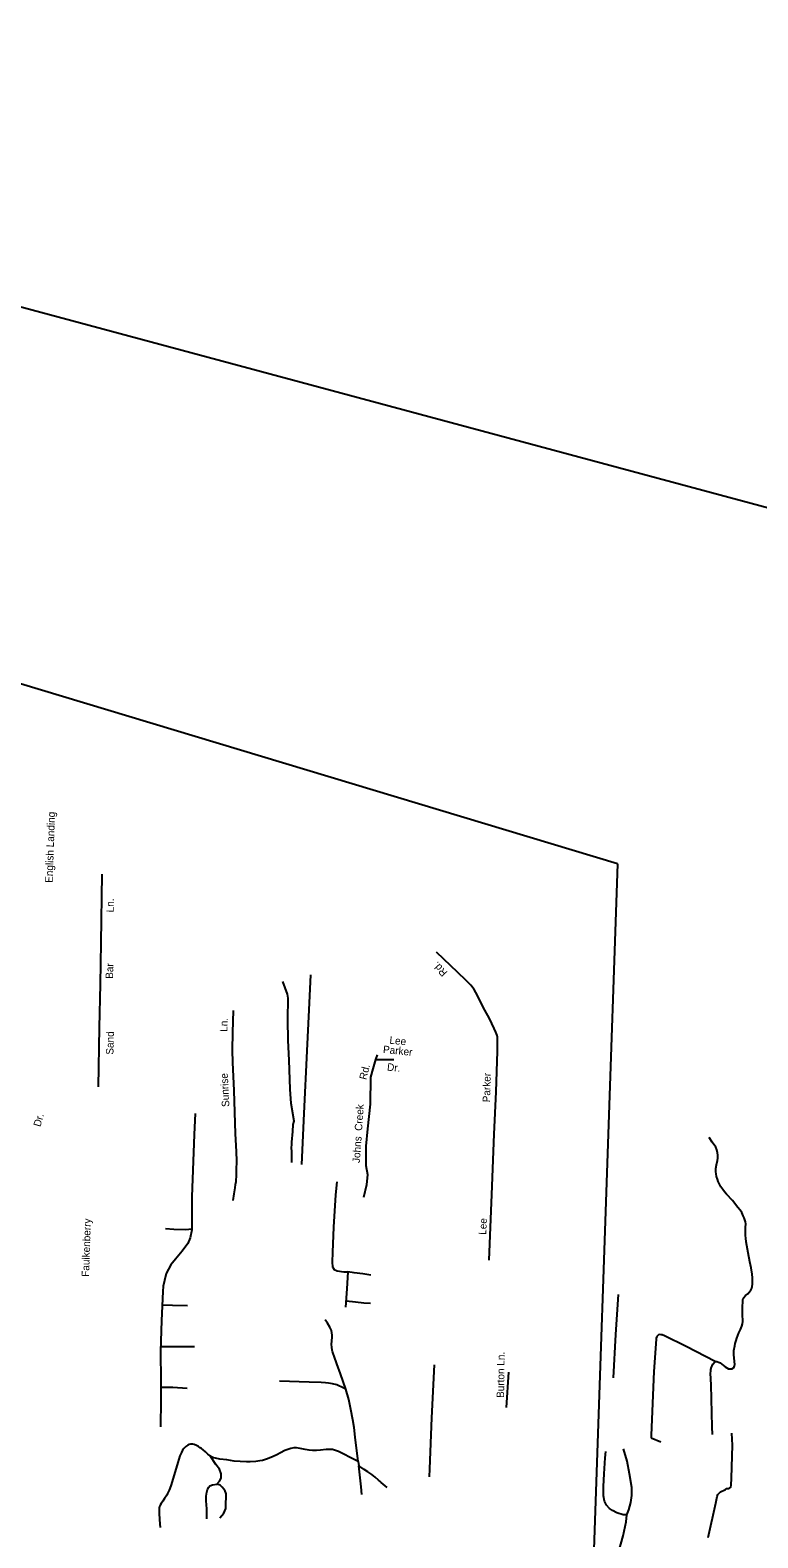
# Model space of a CAD drawing. Extents: x 2308163 to 2335412, y -96774 to 127732.
# Drawn here: x 2321093 to 2321492, y 33932 to 34759 of the extents above; entities that cross this region are included whole.
import ezdxf

# ---------------------------------------------------------------- set-up
doc = ezdxf.new("R2010")
doc.units = 0
for name, color, linetype in [('Old_Level_10', 7, 'Continuous'), ('Old_Level_35', 7, 'Continuous'), ('Old_Level_63', 7, 'Continuous')]:
    doc.layers.add(name, color=color, linetype=linetype)

msp = doc.modelspace()

# ---------------------------------------------------------------- linework, layer by layer
at = {"layer": 'Old_Level_35'}
for p, q in [((2321466.96, 33988.55), (2321466.84, 33992.81)), ((2321433.44, 33988.19), (2321433.38, 33986.76)), ((2321433.38, 33986.76), (2321438.59, 33984.65)), ((2321272.6, 33973.76), (2321272.92, 33971.39)), ((2321274.22, 33959.93), (2321272.92, 33971.39)), ((2321311.78, 33965.37), (2321311.95, 33969.72)), ((2321274.7, 33955.69), (2321274.22, 33959.93)), ((2321163.71, 33941.82), (2321163.94, 33937.59))]:
    msp.add_line(p, q, dxfattribs=at)
for points in [[(2321130.26, 34179.54), (2321130.8, 34212.04), (2321131.25, 34235.79), (2321131.67, 34258.53), (2321132.2, 34296.16)], [(2321344.45, 34084.22), (2321345.93, 34120.3), (2321347.24, 34153.41), (2321348.31, 34176.76), (2321349.1, 34199.01), (2321349.09, 34200.83), (2321349.1, 34203.06), (2321349.11, 34205.26), (2321349.04, 34206.75), (2321348.81, 34207.65), (2321348.23, 34209.41), (2321347.28, 34211.56), (2321344.65, 34216.88), (2321342.14, 34221.56), (2321337.24, 34231.31), (2321336.35, 34232.97), (2321334.47, 34235.25), (2321331.79, 34238.07), (2321327.38, 34242.19), (2321315.52, 34253.34)], [(2321241.64, 34136.86), (2321242.99, 34164.76), (2321244.71, 34199.23), (2321245.74, 34221.72), (2321246.59, 34240.95)], [(2321236.18, 34137.95), (2321236.19, 34143.86), (2321236.14, 34146.21), (2321236.29, 34147.71), (2321236.33, 34149.1), (2321236.83, 34154.95), (2321237.06, 34158.7), (2321237.48, 34160.69), (2321235.95, 34170.36), (2321235.4, 34178.25), (2321234.79, 34194.15), (2321234.18, 34204.91), (2321233.96, 34216.43), (2321234.23, 34228.17), (2321233.79, 34230.32), (2321231.34, 34237.24)], [(2321205.42, 34153.58), (2321204.62, 34177.48), (2321203.87, 34192.76), (2321203.65, 34199.53), (2321203.89, 34209.27), (2321204.3, 34221.4)], [(2321283.04, 34197.1), (2321282.16, 34194.43), (2321280.72, 34189.41), (2321279.44, 34184.7), (2321279.25, 34169.96), (2321277.83, 34156.38), (2321276.87, 34146.9), (2321276.82, 34136.28), (2321277.76, 34131.33), (2321277.25, 34125.64), (2321275.48, 34118.63)], [(2321282.16, 34194.43), (2321292.18, 34194.4)], [(2321183.19, 34164.83), (2321182.6, 34153.21), (2321181.43, 34119.04), (2321181.32, 34105.51), (2321181.31, 34101.05), (2321180.5, 34096.49), (2321179.12, 34093.47), (2321176.12, 34089.29), (2321172.4, 34084.79), (2321169.8, 34081.67), (2321167.35, 34077.05), (2321166.3, 34073.24), (2321165.58, 34070.11), (2321165.48, 34067.05), (2321164.71, 34051.12), (2321164.23, 34034.11), (2321164.39, 34018.07), (2321164.38, 34007.38), (2321164.24, 33992.78)], [(2321204.04, 34117.11), (2321204.62, 34120.72), (2321205.22, 34123.96), (2321205.37, 34125.83), (2321205.67, 34127.45), (2321205.88, 34131.2), (2321205.94, 34133.82), (2321206.08, 34138.66), (2321205.94, 34143.95), (2321205.42, 34153.58)], [(2321468.51, 34028.67), (2321468.9, 34028.68), (2321469.41, 34028.68), (2321470.27, 34028.39), (2321471.38, 34027.87), (2321472.13, 34027.22), (2321473.98, 34025.81), (2321474.94, 34025.14), (2321475.77, 34024.73), (2321476.77, 34024.61), (2321477.69, 34024.7), (2321478.47, 34025.2), (2321478.84, 34025.67), (2321479.1, 34026.33), (2321479.26, 34027.05), (2321478.74, 34032.31), (2321478.78, 34033.68), (2321478.81, 34034.69), (2321479.25, 34037.29), (2321479.53, 34038.55), (2321479.95, 34040.29), (2321480.36, 34041.52), (2321480.88, 34042.9), (2321481.55, 34044.5), (2321482.3, 34046.21), (2321483.13, 34048.1), (2321483.55, 34049.45), (2321483.69, 34050.58), (2321483.61, 34051.58), (2321483.53, 34053.71), (2321483.46, 34055.97), (2321483.53, 34058.96), (2321483.6, 34061.46), (2321483.74, 34062.45), (2321483.83, 34063.25), (2321484.18, 34063.88), (2321485.18, 34064.91), (2321486.32, 34065.88), (2321487.22, 34066.75), (2321487.99, 34067.86), (2321488.54, 34068.89), (2321488.86, 34069.89), (2321488.96, 34071.21), (2321488.97, 34072.58), (2321488.9, 34074.59), (2321488.71, 34076.59), (2321488.18, 34080.1), (2321487.48, 34083.37), (2321486.62, 34088.39), (2321485.5, 34094.43), (2321485.25, 34096.34), (2321485.1, 34097.81), (2321485.05, 34099.7), (2321485.2, 34102.3), (2321485.25, 34104.19), (2321485.14, 34105.31), (2321484.81, 34106.44), (2321484.39, 34107.48), (2321483.85, 34108.73), (2321483.05, 34110.39), (2321482.18, 34111.76), (2321480.96, 34113.29), (2321478.05, 34116.98), (2321474.75, 34120.57), (2321473.66, 34121.84), (2321472.69, 34123.13), (2321471.62, 34124.64), (2321470.85, 34125.99), (2321470.15, 34127.5), (2321469.71, 34128.69), (2321469.25, 34130.32), (2321469.02, 34131.72), (2321468.93, 34132.72), (2321468.92, 34134.61), (2321469.14, 34136.6), (2321469.7, 34139.08), (2321469.94, 34140.31), (2321469.99, 34141.99), (2321469.8, 34143.2), (2321469.34, 34144.96), (2321468.89, 34146.35), (2321466.82, 34149.15), (2321465.13, 34151.56)], [(2321261.01, 34127.38), (2321260.24, 34120.24), (2321259.14, 34102.39), (2321258.51, 34088.76), (2321258.32, 34083.24), (2321258.55, 34080.63), (2321259.48, 34079.13), (2321261.08, 34078.43), (2321264.8, 34077.97), (2321266.92, 34077.9)], [(2321181.31, 34101.38), (2321178.02, 34100.95), (2321171.47, 34101.18), (2321166.89, 34101.55)], [(2321266.92, 34077.9), (2321266.43, 34068.65), (2321265.76, 34058.6)], [(2321279.54, 34076.16), (2321275.17, 34076.8), (2321270.47, 34077.29), (2321266.92, 34077.9)], [(2321412.79, 34019.77), (2321414, 34043.51), (2321415.4, 34065.49)], [(2321165.12, 34059.73), (2321170.69, 34059.66), (2321179, 34059.37)], [(2321265.98, 34061.92), (2321271.23, 34061.5), (2321275.76, 34060.85), (2321279.34, 34060.73)], [(2321265.93, 34013.43), (2321263.02, 34021.91), (2321260.9, 34027.33), (2321259.4, 34031.56), (2321258.84, 34033.16), (2321258.57, 34034.26), (2321258.36, 34034.88), (2321258.11, 34036.52), (2321258.04, 34038.03), (2321258.19, 34040.02), (2321258.37, 34042.01), (2321258.4, 34043.14), (2321258.27, 34044.35), (2321257.96, 34045.66), (2321257.13, 34047.54), (2321255.81, 34049.71), (2321254.61, 34051.48)], [(2321468.51, 34028.67), (2321452.6, 34036.94), (2321440.73, 34042.74), (2321439.5, 34043.27), (2321438.88, 34043.41), (2321438.16, 34043.46), (2321437.4, 34043.26), (2321436.85, 34042.82), (2321436.49, 34042.33), (2321436.18, 34041.51), (2321436.19, 34040.97), (2321434.88, 34023.24), (2321433.44, 33988.19)], [(2321164.31, 34036.86), (2321169.91, 34036.94), (2321182.82, 34036.94)], [(2321311.95, 33969.72), (2321313.07, 33997.68), (2321314.42, 34026.9)], [(2321354.01, 34003.38), (2321355.27, 34022.76)], [(2321466.84, 33992.81), (2321466.22, 34015.85), (2321466, 34022.24), (2321466.02, 34023.37), (2321466.09, 34024.29), (2321466.46, 34025.49), (2321466.82, 34026.35), (2321467.25, 34027.21), (2321468.51, 34028.67)], [(2321178.74, 34013.9), (2321170.88, 34014.39), (2321164.39, 34014.47)], [(2321265.93, 34013.43), (2321263.71, 34014.51), (2321262.11, 34015.28), (2321260.85, 34015.81), (2321258.49, 34016.51), (2321256.38, 34016.81), (2321254.64, 34016.97), (2321252.26, 34017.16), (2321245.76, 34017.31), (2321229.52, 34017.84)], [(2321272.6, 33973.76), (2321270.92, 33987.06), (2321270.42, 33992.47), (2321269.78, 33996.58), (2321268.67, 34002.38), (2321267.43, 34007.91), (2321265.93, 34013.43)], [(2321188.93, 33979.04), (2321187.59, 33980.12), (2321186.6, 33980.84), (2321185.98, 33981.37), (2321185.12, 33982.02), (2321183.99, 33982.59), (2321182.66, 33983.07), (2321181.88, 33983.29), (2321180.67, 33983.37), (2321179.91, 33983.14), (2321179.15, 33982.79), (2321178.13, 33982.04), (2321176.97, 33980.95), (2321176.32, 33980.09), (2321175.63, 33978.67), (2321174.88, 33976.88), (2321173.67, 33973.17), (2321170.66, 33962.86), (2321169.86, 33960.38), (2321169.01, 33958.14), (2321168.03, 33956.17), (2321167.61, 33955.3), (2321166.45, 33953.47), (2321165.39, 33951.97), (2321164.62, 33950.74), (2321163.96, 33949.87), (2321163.7, 33949.14), (2321163.42, 33948.15), (2321163.4, 33947.29), (2321163.49, 33945.65), (2321163.71, 33941.82)], [(2321464.69, 33932.11), (2321468.9, 33951.01), (2321469.54, 33954.62), (2321470.02, 33955.75), (2321470.78, 33956.59), (2321471.43, 33957.09), (2321472.06, 33957.44), (2321473.07, 33957.92), (2321474.09, 33958.39), (2321474.84, 33958.89), (2321475.12, 33958.93), (2321475.83, 33959.06), (2321476.55, 33959.35), (2321477.03, 33959.73), (2321477.23, 33960.83), (2321477.52, 33964.68), (2321477.91, 33982.7), (2321477.58, 33989.26)], [(2321272.6, 33973.76), (2321268.66, 33975.88), (2321264.44, 33978.09), (2321261.86, 33979.29), (2321259.74, 33980.1), (2321258.51, 33980.38), (2321257.01, 33980.39), (2321255.13, 33980.32), (2321251.99, 33980.02), (2321249.74, 33979.92), (2321247.61, 33979.87), (2321245.74, 33980.05), (2321243.51, 33980.36), (2321240.88, 33980.92), (2321238.77, 33981.22), (2321237.25, 33981.25), (2321235.75, 33980.92), (2321234.51, 33980.56), (2321232.36, 33979.75), (2321230.07, 33978.55), (2321228.04, 33977.48), (2321226.02, 33976.52), (2321223.87, 33975.57), (2321222.36, 33974.99), (2321220.21, 33974.42), (2321218.71, 33974.19), (2321216.58, 33973.87), (2321213.43, 33973.67), (2321211.38, 33973.64), (2321207.83, 33973.77), (2321204.57, 33974.04), (2321200.57, 33974.63), (2321196.72, 33975.11), (2321194.36, 33975.55), (2321193.29, 33975.89), (2321192.24, 33976.33), (2321191.38, 33976.86), (2321190.16, 33977.76), (2321188.93, 33979.04)], [(2321196.78, 33942.83), (2321198.99, 33945.36), (2321199.98, 33947.97), (2321200.1, 33951.35), (2321200.24, 33953.69), (2321200.28, 33954.96), (2321200.26, 33955.98), (2321200.08, 33956.62), (2321199.64, 33957.56), (2321198.94, 33958.62), (2321197.97, 33959.77), (2321196.85, 33960.85), (2321195.03, 33961.35), (2321196.52, 33962.96), (2321197.53, 33964.73), (2321197.54, 33967.02), (2321196.62, 33969.66), (2321194.62, 33972.08), (2321191.38, 33976.86)], [(2321420.09, 33944.43), (2321417.97, 33944.5), (2321414.46, 33945.56), (2321412.15, 33946.82), (2321410.54, 33948.06), (2321408.94, 33949.77), (2321407.83, 33951.93), (2321407.23, 33955.02), (2321407.17, 33959.98), (2321407.65, 33967.04), (2321408.18, 33975.76), (2321408.57, 33979.31)], [(2321420.09, 33944.43), (2321421.13, 33947.22), (2321422.22, 33951.2), (2321422.83, 33955.19), (2321422.74, 33959.44), (2321421.58, 33967.03), (2321420.17, 33973.93), (2321418.22, 33980.74)], [(2321284.68, 33962.9), (2321283.87, 33963.63), (2321281.99, 33965.2), (2321280.18, 33966.59), (2321277.96, 33968.15), (2321275.88, 33969.46), (2321272.92, 33971.39)], [(2321189.58, 33942.28), (2321189.66, 33947.88), (2321189.3, 33952.18), (2321189.33, 33954.83), (2321189.54, 33956.97), (2321189.92, 33958.37), (2321190.64, 33959.62), (2321191.3, 33960.5), (2321192.7, 33961.06), (2321195.03, 33961.35)], [(2321288.6, 33959.61), (2321285.33, 33962.33), (2321284.68, 33962.9)], [(2321414.17, 33916.54), (2321415.09, 33922.65), (2321418.04, 33932.93), (2321419.73, 33940.66), (2321420.09, 33944.43)]]:
    msp.add_lwpolyline(points, dxfattribs=at)
at = {"layer": 'Old_Level_63'}
msp.add_line((2321414.95, 34301.9), (2320906.85, 34455.15), dxfattribs=at)
for points in [[(2322212.45, 34280.74), (2322047.32, 34349.18), (2320522.37, 34759.49)], [(2321414.95, 34301.9), (2321386.61, 33480.39), (2320873.79, 33496.58), (2320906.85, 34455.15)]]:
    msp.add_lwpolyline(points, dxfattribs=at)

# ---------------------------------------------------------------- texts
at = {"layer": 'Old_Level_10'}
for s, rotation, p in [('English Landing', 88.02472, (2321105, 34291.39)), ('Ln.', 89.09894, (2321138.51, 34275.21)), ('Bar', 88.11968, (2321138.12, 34238.7)), ('Rd.', 132.96342, (2321321.87, 34242.33)), ('Ln.', 88.06245, (2321200.82, 34209.63)), ('Sand', 88.91581, (2321138.36, 34197.09)), ('Lee', 354.29253, (2321289.67, 34203.15)), ('Parker', 354.29253, (2321286.11, 34198.06)), ('Rd.', 76.19135, (2321277.11, 34183.06)), ('Dr.', 354.29253, (2321288.33, 34188.4)), ('Sunrise', 92.81928, (2321201.98, 34168.51)), ('Parker', 88.71928, (2321345.01, 34170.94)), ('Dr.', 74.27871, (2321098.31, 34157.23)), ('Johns  Creek ', 86.04842, (2321273.53, 34137.55)), ('Faulkenberry', 88.13773, (2321124.99, 34075.14)), ('Lee', 86.89247, (2321342.83, 34098.15)), ('Burton Ln.', 89.29773, (2321352.66, 34008.67))]:
    msp.add_text(s, height=4.101, rotation=rotation, dxfattribs=at).set_placement(p)

doc.saveas('drawing.dxf')
